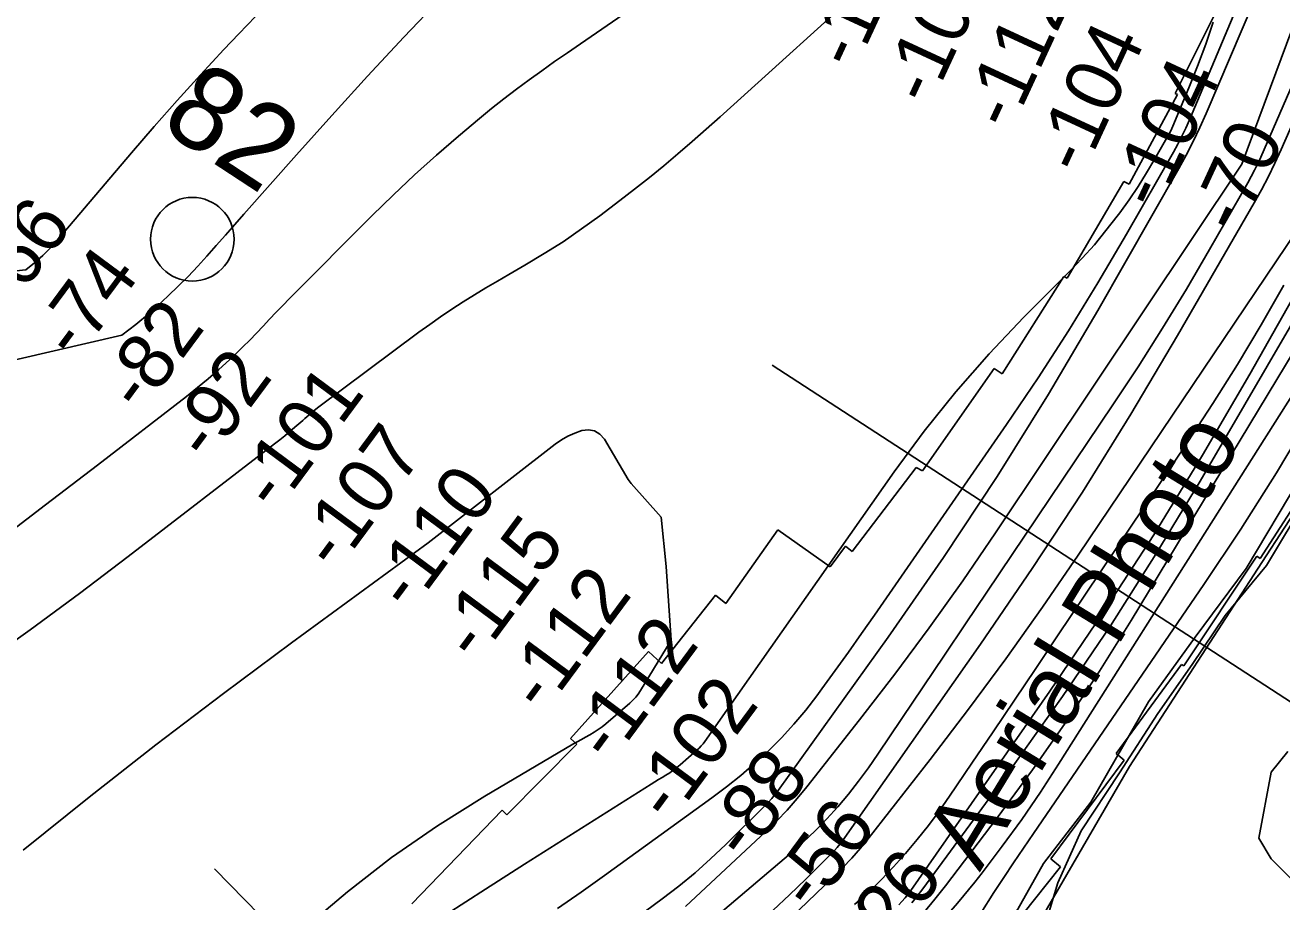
# Model space of a CAD drawing. Extents: x 3715084 to 3753216, y 488173 to 513963.
# Drawn here: x 3732951 to 3734453, y 500658 to 501705 of the extents above; entities that cross this region are included whole.
import ezdxf

# ---------------------------------------------------------------- set-up
doc = ezdxf.new("R2010")
doc.units = 0
for name, color, linetype in [('V-RIVR-EDGE', 7, 'Continuous'), ('V-RIVR-IDEN', 7, 'Continuous'), ('V-RIVR-MILE', 7, 'Continuous'), ('V-RIVR-RANG', 7, 'Continuous'), ('V-RRAP-FSHR', 7, 'Continuous'), ('V-RRAP-RVMT', 7, 'Continuous'), ('V-SITE-VEGE', 7, 'Continuous'), ('V-TOPO-DPTH', 7, 'Continuous'), ('V-TOPO-MAJR', 7, 'Continuous'), ('V-TOPO-MINR', 7, 'Continuous'), ('V-TOPO-WATR', 7, 'Continuous'), ('V-WETL-SWMP', 7, 'Continuous')]:
    doc.layers.add(name, color=color, linetype=linetype)

msp = doc.modelspace()

# ---------------------------------------------------------------- linework, layer by layer
at = {"layer": 'V-RIVR-EDGE'}
msp.add_lwpolyline([(3733369, 500005.2), (3733444.2, 500062.7), (3733485.1, 500102.8), (3733526.6, 500135.1), (3733637.3, 500198.5), (3733683.5, 500203.1), (3733754.4, 500243.8), (3733821.7, 500271.2), (3733871.6, 500298.7), (3733951.6, 500355.6), (3734004.6, 500401.7), (3734035.9, 500462.2), (3734076.9, 500541.4), (3734102.9, 500604.3), (3734137.2, 500649.3), (3734168, 500703.8), (3734224.6, 500776.9), (3734293.3, 500896.8), (3734349.4, 500974.1), (3734410.2, 501056.2), (3734538.6, 501271.4)], dxfattribs=at)
at = {"layer": 'V-RIVR-MILE'}
msp.add_circle((3733150.5, 501449.5), 50, dxfattribs=at)
at = {"layer": 'V-RIVR-RANG'}
for p, q in [((3734749.4, 500710.8), (3733843.8, 501299.2)), ((3733877.6, 499983.6), (3733177.1, 500697.2))]:
    msp.add_line(p, q, dxfattribs=at)
at = {"layer": 'V-RRAP-FSHR'}
msp.add_lwpolyline([(3735311.1, 503785.3), (3735300.2, 503529), (3735290.8, 503381.7), (3735268.1, 503216.8), (3735221.1, 502972.3), (3735143.6, 502689.5), (3735049.1, 502444.9), (3734990, 502275), (3734953.7, 502144.5), (3734837, 501859.4), (3734782.6, 501733.3), (3734721.8, 501591.9), (3734612.9, 501392.2), (3734511.3, 501189.8), (3734429.1, 501063.2), (3734270.7, 500819.7), (3734116.5, 500553.8), (3734048, 500419.9), (3733930.7, 500312.6), (3733803.5, 500233.2), (3733597.2, 500150), (3733341.9, 499958.2)], dxfattribs=at)
at = {"layer": 'V-RRAP-RVMT'}
for p, q in [((3734393.5, 501759.7), (3734325.5, 501623.7)), ((3734328.3, 501622.3), (3734270.4, 501515.5)), ((3734325.5, 501623.7), (3734328.3, 501622.3)), ((3734264.2, 501518.5), (3734196.4, 501403.2)), ((3734270.4, 501515.5), (3734264.2, 501518.5)), ((3734192.3, 501405.2), (3734118.4, 501288.7)), ((3734196.4, 501403.2), (3734192.3, 501405.2)), ((3734109.1, 501294.9), (3734023.5, 501172.7)), ((3734118.4, 501288.7), (3734109.1, 501294.9)), ((3734427, 501068.2), (3734512.2, 501200.3)), ((3734015.7, 501176.8), (3733939.2, 501076.3)), ((3734023.5, 501172.7), (3734015.7, 501176.8)), ((3733850.3, 501102.3), (3733788.1, 501014.5)), ((3733912.8, 501058.3), (3733850.3, 501102.3)), ((3733931.3, 501082.8), (3733912.8, 501058.3)), ((3733939.2, 501076.3), (3733931.3, 501082.8)), ((3734335.9, 500940), (3734423.1, 501070.8)), ((3734423.1, 501070.8), (3734427, 501068.2)), ((3733776, 501024.2), (3733711.5, 500942.8)), ((3733788.1, 501014.5), (3733776, 501024.2)), ((3733695.9, 500956.9), (3733602.5, 500853.2)), ((3733711.5, 500942.8), (3733695.9, 500956.9)), ((3734254.8, 500835), (3734332.9, 500941.5)), ((3734332.9, 500941.5), (3734335.9, 500940)), ((3733610.3, 500846.4), (3733526.5, 500761.7)), ((3733602.5, 500853.2), (3733610.3, 500846.4)), ((3734176.9, 500709.4), (3734264.4, 500827)), ((3734264.4, 500827), (3734254.8, 500835)), ((3733520.8, 500767.3), (3733412.7, 500655.4)), ((3733526.5, 500761.7), (3733520.8, 500767.3)), ((3734188.1, 500699.6), (3734176.9, 500709.4)), ((3734095.6, 500583.7), (3734188.1, 500699.6))]:
    msp.add_line(p, q, dxfattribs=at)
at = {"layer": 'V-SITE-VEGE'}
msp.add_lwpolyline([(3734173.6, 500642.3), (3734185, 500680.5), (3734213.1, 500742.8), (3734258.9, 500812.2), (3734304.8, 500882.9), (3734345.6, 500941.4), (3734385.1, 501000), (3734434.7, 501059.8), (3734483.1, 501140.6)], dxfattribs=at)
at = {"layer": 'V-TOPO-DPTH'}
for points in [[(3734495.9, 501497), (3734209.5, 501071.9), (3734166.8, 501009.8), (3734123.1, 500948.4), (3734078.2, 500887.9), (3734032.4, 500828.1), (3733959.5, 500734.7), (3733949.3, 500722.2), (3733938.7, 500710.1), (3733927.7, 500698.4), (3733916.2, 500687), (3733836, 500610.3)], [(3734495.9, 501497), (3734209.5, 501071.9), (3734166.8, 501009.8), (3734123.1, 500948.4), (3734078.2, 500887.9), (3734032.4, 500828.1), (3733959.5, 500734.7), (3733949.3, 500722.2), (3733938.7, 500710.1), (3733927.7, 500698.4), (3733916.2, 500687), (3733836, 500610.3)], [(3734509.2, 501455.3), (3734414.6, 501288.4), (3734358, 501191.7), (3734299.7, 501096.2), (3734238.6, 501002.3), (3734175.7, 500909.6), (3734009.2, 500671.3), (3734005.9, 500666.8), (3734002.5, 500662.5), (3733998.8, 500658.3), (3733995, 500654.3)], [(3734509.2, 501455.3), (3734414.6, 501288.4), (3734358, 501191.7), (3734299.7, 501096.2), (3734238.6, 501002.3), (3734175.7, 500909.6), (3734009.2, 500671.3), (3734005.9, 500666.8), (3734002.5, 500662.5), (3733998.8, 500658.3), (3733995, 500654.3)], [(3734025.2, 500645.7), (3734038.2, 500661.1), (3734050.8, 500676.9), (3734112.6, 500758.3), (3734154.8, 500815.7), (3734195.8, 500874), (3734234.9, 500933.6), (3734272.8, 500994), (3734523.1, 501407.7)], [(3734025.2, 500645.7), (3734038.2, 500661.1), (3734050.8, 500676.9), (3734112.6, 500758.3), (3734154.8, 500815.7), (3734195.8, 500874), (3734234.9, 500933.6), (3734272.8, 500994), (3734523.1, 501407.7)], [(3733942.2, 500654.8), (3733958.2, 500669.2), (3733973.8, 500684.1), (3733988.7, 500699.7), (3734003.1, 500715.6), (3734017, 500732.2), (3734030.4, 500749), (3734043.2, 500766.4), (3734055.6, 500784), (3734082.4, 500823.6), (3734107.8, 500861.2), (3734133.3, 500898.9), (3734158.7, 500936.7), (3734184, 500974.4), (3734340.4, 501207.4), (3734370.5, 501253.4), (3734399.8, 501299.9), (3734428, 501347.1), (3734455.4, 501394.8)], [(3733942.2, 500654.8), (3733958.2, 500669.2), (3733973.8, 500684.1), (3733988.7, 500699.7), (3734003.1, 500715.6), (3734017, 500732.2), (3734030.4, 500749), (3734043.2, 500766.4), (3734055.6, 500784), (3734082.4, 500823.6), (3734107.8, 500861.2), (3734133.3, 500898.9), (3734158.7, 500936.7), (3734184, 500974.4), (3734340.4, 501207.4), (3734370.5, 501253.4), (3734399.8, 501299.9), (3734428, 501347.1), (3734455.4, 501394.8)], [(3734487, 501238.6), (3734446.4, 501170.3), (3734403.8, 501103.3), (3734359.8, 501037.1), (3734155.9, 500739.6), (3734144, 500722), (3734132.2, 500704.4), (3734120.4, 500686.8), (3734108.8, 500669), (3734092.9, 500644.5), (3734089.2, 500639.1), (3734085.4, 500633.7), (3734081.4, 500628.4), (3734077.3, 500623.2), (3734073.1, 500618.1), (3734068.6, 500613.2), (3734064, 500608.6), (3734059.2, 500604.1), (3733722, 500302.9), (3733654.9, 500244.3), (3733587.1, 500186.7), (3733518.1, 500130.6), (3733448.3, 500075.5), (3733325.3, 499980.5)]]:
    msp.add_lwpolyline(points, dxfattribs=at)
at = {"layer": 'V-TOPO-MAJR'}
for points in [[(3733844.9, 500648), (3733864.5, 500666.3), (3733883.7, 500684.9), (3733914.6, 500715.5), (3733918.1, 500719.2), (3733921.4, 500722.9), (3733924.5, 500726.8), (3733927.5, 500730.8), (3734092.8, 500965.8), (3734154.6, 501056.1), (3734214.7, 501147.5), (3734272.3, 501240.4), (3734328.3, 501334.4), (3734419.8, 501493), (3734428.5, 501508.7), (3734436.9, 501524.5), (3734444.7, 501540.6), (3734452.2, 501556.9), (3734749, 502229.8)], [(3733952, 501750.3), (3733797.9, 501610.7), (3733781.3, 501595.8), (3733764.7, 501580.9), (3733747.9, 501566.2), (3733731, 501551.6), (3733714, 501537.2), (3733696.8, 501523.1), (3733679.2, 501509.3), (3733661.6, 501495.7), (3733637.5, 501477.6), (3733615.8, 501461.8), (3733593.6, 501446.6), (3733570.9, 501432.3), (3733547.9, 501418.4), (3733529, 501407.6), (3733515.2, 501399.5), (3733501.4, 501391.4), (3733487.7, 501383), (3733474.1, 501374.6), (3733460.6, 501365.9), (3733447.3, 501357), (3733434.2, 501347.8), (3733421.3, 501338.4), (3733300.3, 501248), (3733297.7, 501246), (3733295.1, 501244), (3733292.5, 501241.9), (3733290, 501239.7), (3733287.5, 501237.5), (3733285, 501235.3), (3733282.5, 501233.1), (3733280, 501231), (3733273.1, 501224.9), (3733267.1, 501219.8), (3733261.1, 501214.7), (3733254.9, 501209.7), (3733248.7, 501204.9), (3733073.7, 501070.5), (3733015.5, 501026.4), (3732956.7, 500983), (3732897.3, 500940.5)], [(3733454.1, 500642.6), (3733500.8, 500672.9), (3733547.7, 500702.9), (3733698.9, 500798.3), (3733703.3, 500801.1), (3733707.8, 500803.9), (3733712.2, 500806.6), (3733716.7, 500809.4), (3733721.1, 500812.2), (3733725.4, 500815.2), (3733729.6, 500818.4), (3733733.6, 500821.7), (3733753.6, 500839.1), (3733756.2, 500841.5), (3733758.7, 500844.1), (3733761, 500846.8), (3733763.1, 500849.6), (3733989.4, 501171.7), (3734025.4, 501220.2), (3734063, 501267.4), (3734102.9, 501312.5), (3734144.5, 501356.4), (3734199.2, 501411.1), (3734214.2, 501426.8), (3734228.8, 501443), (3734242.6, 501459.8), (3734256, 501477), (3734259.1, 501481.2), (3734270.2, 501496.8), (3734281, 501512.7), (3734291.2, 501528.9), (3734301.1, 501545.5), (3734317.1, 501573.5), (3734318.6, 501576.2), (3734320, 501578.9), (3734321.3, 501581.7), (3734322.5, 501584.5), (3734341.7, 501630.5), (3734352, 501656.4), (3734361.9, 501682.6), (3734370.9, 501709)]]:
    msp.add_lwpolyline(points, dxfattribs=at)
at = {"layer": 'V-TOPO-MINR'}
for points in [[(3733740, 500652.4), (3733836.1, 500742), (3733849, 500754.6), (3733861.5, 500767.6), (3733873.4, 500781.2), (3733884.9, 500795.1), (3733948.1, 500875.2), (3733990.2, 500929.9), (3734031.4, 500985.3), (3734071.4, 501041.6), (3734110.5, 501098.6), (3734405.2, 501539.2), (3734708.8, 502355)], [(3733355.6, 500047.3), (3733365.1, 500054.6), (3733374.7, 500061.9), (3733384.3, 500069.1), (3733520.1, 500171), (3733596.7, 500230.3), (3733672, 500291.1), (3733745.3, 500354.2), (3733817.4, 500418.9), (3733998.3, 500586.2), (3734021.5, 500608.7), (3734043.9, 500631.9), (3734065.2, 500656.2), (3734085.7, 500681.2), (3734094.6, 500692.7), (3734118.6, 500724.3), (3734141.9, 500756.3), (3734164.2, 500789), (3734185.9, 500822.2), (3734586.6, 501454.8), (3734909.7, 502280.4)], [(3733692.1, 500646.6), (3733712.3, 500661.3), (3733732.1, 500676.7), (3733751.5, 500692.5), (3733770.1, 500709.2), (3733788.3, 500726.4), (3733834.6, 500772.1), (3733838.9, 500776.5), (3733843.1, 500781.2), (3733847, 500786), (3733850.8, 500791), (3733982.3, 500974.1), (3734048.5, 501069.4), (3734112.7, 501165.9), (3734173.8, 501264.5), (3734232.9, 501364.3), (3734329.7, 501533.9), (3734338.6, 501550.1), (3734347, 501566.4), (3734354.9, 501583), (3734362.4, 501599.7), (3734642.4, 502256.1)], [(3733587.1, 500649.8), (3733615.3, 500669.3), (3733643.2, 500689.2), (3733771.4, 500782), (3733789, 500795.3), (3733806.2, 500809), (3733822.9, 500823.4), (3733839.1, 500838.3), (3733854.7, 500853.9), (3733869.6, 500870), (3733883.7, 500886.9), (3733897.2, 500904.2), (3733903.1, 500912.4), (3733919.1, 500934.2), (3733934.9, 500956.2), (3733950.6, 500978.3), (3733966.1, 501000.5), (3734123.8, 501228), (3734161.4, 501283.8), (3734198, 501340.2), (3734233.1, 501397.5), (3734267.3, 501455.5), (3734323.4, 501553.7), (3734328.6, 501563.1), (3734333.5, 501572.7), (3734338, 501582.3), (3734342.4, 501592.2), (3734414.9, 501764.6)], [(3733715.5, 501752.5), (3733614.5, 501683.1), (3733599, 501672.4), (3733583.6, 501661.7), (3733568.3, 501650.8), (3733553, 501639.9), (3733537.9, 501628.8), (3733522.9, 501617.4), (3733508.2, 501605.7), (3733493.7, 501593.7), (3733468.8, 501572.7), (3733442.2, 501549.8), (3733416.1, 501526.4), (3733390.6, 501502.3), (3733365.5, 501477.8), (3733266.7, 501378.7), (3733258.6, 501370.5), (3733250.7, 501362.3), (3733242.8, 501354), (3733235, 501345.6), (3733227.1, 501337.2), (3733219.2, 501329), (3733211, 501320.9), (3733202.8, 501313), (3733194.8, 501305.5), (3733182.3, 501294.1), (3733169.6, 501282.9), (3733156.6, 501272.2), (3733143.4, 501261.6), (3733037.1, 501179.6), (3732975, 501132.1), (3732912.8, 501085)], [(3733705.4, 500579.9), (3733866, 500716), (3733880.8, 500729.1), (3733895.1, 500742.7), (3733908.8, 500756.9), (3733922.1, 500771.5), (3733934.7, 500786.7), (3733947, 500802.2), (3733958.7, 500818.1), (3733970, 500834.3), (3733998.7, 500877), (3734024.1, 500914.7), (3734049.5, 500952.5), (3734074.9, 500990.2), (3734100.3, 501028), (3734251, 501251.5), (3734281, 501297.1), (3734310.4, 501343.2), (3734338.8, 501389.9), (3734366.5, 501437.1), (3734412.3, 501517.1), (3734416.4, 501524.6), (3734420.4, 501532.2), (3734424.1, 501539.9), (3734427.6, 501547.7), (3734518.7, 501756.7)], [(3733446.7, 501736.9), (3733403.2, 501690.8), (3733360, 501644.3), (3733317.3, 501597.4), (3733274.9, 501550.2), (3733212.1, 501479.4), (3733201.1, 501467), (3733190.1, 501454.5), (3733179, 501442), (3733168, 501429.5), (3733156.9, 501417.2), (3733145.5, 501405.1), (3733133.7, 501393.3), (3733121.7, 501381.8), (3733114.9, 501375.6), (3733099.1, 501361.4), (3733082.9, 501347.8), (3733066.1, 501334.8), (3732380.8, 501176.6)], [(3733225.8, 501715.7), (3733206.1, 501695.1), (3733188.3, 501676.3), (3733160.1, 501646), (3733132.2, 501615.4), (3733104.8, 501584.3), (3733077.7, 501552.9), (3732990.2, 501449.8), (3732981.2, 501439.8), (3732971.8, 501430.3), (3732961.8, 501421.5), (3732951.4, 501413), (3732225.5, 501338.5)], [(3733836, 500610.3), (3733916.2, 500687), (3733927.7, 500698.4), (3733938.7, 500710.1), (3733949.3, 500722.2), (3733959.5, 500734.7), (3734032.4, 500828.1), (3734078.2, 500887.9), (3734123.1, 500948.4), (3734166.8, 501009.8), (3734209.5, 501071.9), (3734495.9, 501497)], [(3733995, 500654.3), (3733998.8, 500658.3), (3734002.5, 500662.5), (3734005.9, 500666.8), (3734009.2, 500671.3), (3734175.7, 500909.6), (3734238.6, 501002.3), (3734299.7, 501096.2), (3734358, 501191.7), (3734414.6, 501288.4), (3734509.2, 501455.3)], [(3734010.4, 500656.6), (3734017.1, 500664.8), (3734023.6, 500673.3), (3734131.7, 500820.3), (3734190.7, 500903.3), (3734247.9, 500987.5), (3734302.4, 501073.4), (3734355.1, 501160.6), (3734515.3, 501435.1)], [(3734025.2, 500645.7), (3734038.2, 500661.1), (3734050.8, 500676.9), (3734112.6, 500758.3), (3734154.8, 500815.7), (3734195.8, 500874), (3734234.9, 500933.6), (3734272.8, 500994), (3734523.1, 501407.7)], [(3733942.2, 500654.8), (3733958.2, 500669.2), (3733973.8, 500684.1), (3733988.7, 500699.7), (3734003.1, 500715.6), (3734017, 500732.2), (3734030.4, 500749), (3734043.2, 500766.4), (3734055.6, 500784), (3734082.4, 500823.6), (3734107.8, 500861.2), (3734133.3, 500898.9), (3734158.7, 500936.7), (3734184, 500974.4), (3734340.4, 501207.4), (3734370.5, 501253.4), (3734399.8, 501299.9), (3734428, 501347.1), (3734455.4, 501394.8)], [(3733284.9, 500626.9), (3733335.9, 500670), (3733388.5, 500710.9), (3733443.5, 500748.6), (3733500, 500784.2), (3733605.4, 500846.1), (3733610.4, 500849.1), (3733615.5, 500851.9), (3733620.6, 500854.8), (3733625.7, 500857.6), (3733630.7, 500860.5), (3733635.6, 500863.6), (3733640.3, 500867), (3733644.8, 500870.6), (3733673.5, 500895.3), (3733677.1, 500898.7), (3733680.5, 500902.3), (3733683.6, 500906.2), (3733686.4, 500910.2), (3733722.7, 500970.4), (3733716.8, 501058.7), (3733710.9, 501117.5), (3733675, 501157.6), (3733671.6, 501162.3), (3733643.1, 501210.6), (3733637.6, 501216.5), (3733631.4, 501220.5), (3733624.2, 501221.8), (3733616.2, 501221.1), (3733607.6, 501218), (3733599.4, 501214.3), (3733591.6, 501209.7), (3733584.1, 501204.5), (3733432.5, 501087), (3733269, 500967.2), (3733187.7, 500906.7), (3733107, 500845.4), (3733027.3, 500782.9), (3732948.2, 500719.5)]]:
    msp.add_lwpolyline(points, dxfattribs=at)
at = {"layer": 'V-TOPO-WATR'}
msp.add_lwpolyline([(3733325.3, 499980.5), (3733448.3, 500075.5), (3733518.1, 500130.6), (3733587.1, 500186.7), (3733654.9, 500244.3), (3733722, 500302.9), (3734059.2, 500604.1), (3734064, 500608.6), (3734068.6, 500613.2), (3734073.1, 500618.1), (3734077.3, 500623.2), (3734081.4, 500628.4), (3734085.4, 500633.7), (3734089.2, 500639.1), (3734092.9, 500644.5), (3734108.8, 500669), (3734120.4, 500686.8), (3734132.2, 500704.4), (3734144, 500722), (3734155.9, 500739.6), (3734359.8, 501037.1), (3734403.8, 501103.3), (3734446.4, 501170.3), (3734487, 501238.6)], dxfattribs=at)
at = {"layer": 'V-WETL-SWMP'}
msp.add_lwpolyline([(3734464.9, 500684.4), (3734440.2, 500709.1), (3734425.3, 500733.8), (3734440.2, 500812.8), (3734459.9, 500837.5)], dxfattribs=at)

# ---------------------------------------------------------------- texts
at = {"layer": 'V-RIVR-IDEN'}
for s, height, rotation, p in [('82', 100, 326.7934, (3733109.3, 501583.7)), ('Aerial Photo', 83, 58.5704, (3734091.7, 500692.7))]:
    msp.add_text(s, height=height, rotation=rotation, dxfattribs=at).set_placement(p)
at = {"layer": 'V-RIVR-RANG'}
for s, rotation, p in [('-100', 65.1688, (3733942.3, 501649.6)), ('-105', 65.1688, (3734032.6, 501606.6)), ('-112', 65.1688, (3734129, 501576.9)), ('-104', 65.1688, (3734214.7, 501523.9)), ('-104', 65.1688, (3734305.3, 501481.7)), ('-70', 65.1688, (3734402.2, 501452.8)), ('-66', 53.4651, (3732931.5, 501362.4)), ('-74', 53.4651, (3733011.6, 501302.5)), ('-82', 53.4651, (3733089.7, 501240)), ('-92', 53.4651, (3733170.6, 501181.1)), ('-101', 53.4651, (3733250.9, 501121.6)), ('-107', 53.4651, (3733322.8, 501050.6)), ('-110', 53.4651, (3733411.3, 501002.1)), ('-115', 53.4651, (3733491.1, 500941.8)), ('-112', 53.4651, (3733570.6, 500881.2)), ('-112', 53.4651, (3733650.8, 500821.5)), ('-102', 53.4651, (3733722.3, 500749.9)), ('-88', 53.4651, (3733812.8, 500704.1)), ('-56', 53.4651, (3733892.7, 500644)), ('-26', 53.1783, (3733971.9, 500583.5))]:
    msp.add_text(s, height=67, rotation=rotation, dxfattribs=at).set_placement(p)

doc.saveas('drawing.dxf')
